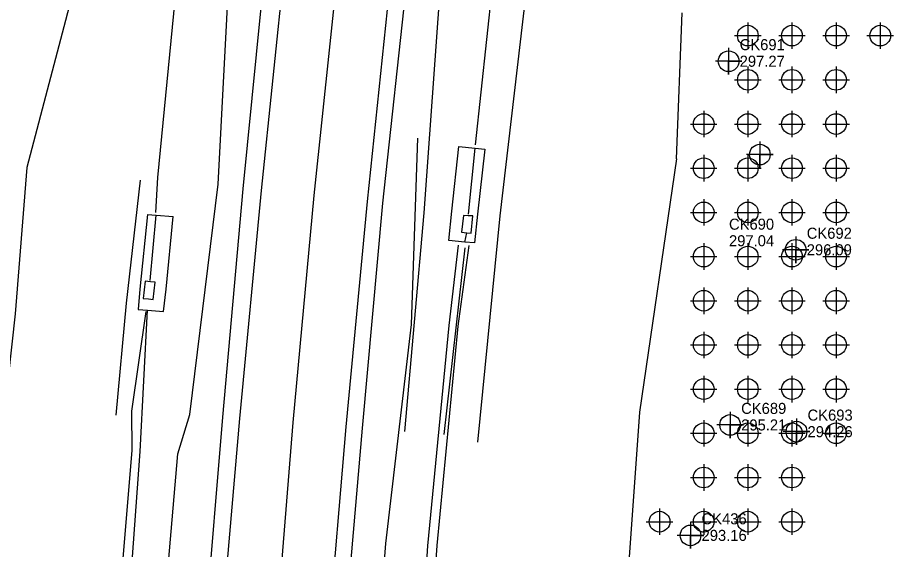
# Model space of a CAD drawing. Extents: x 1941547 to 1942851, y 663002 to 668358.
# Drawn here: x 1941924.5 to 1942123, y 667943.7 to 668064.1 of the extents above; entities that cross this region are included whole.
import ezdxf

# ---------------------------------------------------------------- set-up
doc = ezdxf.new("R2010")
doc.units = 0
for name, color, linetype in [('CTL GPS Vertical Cogo Elevation', 7, 'Continuous'), ('CTL NGS Vertical CELL', 7, 'Continuous'), ('Exist DTM Drainline Cogo Elevation', 7, 'Continuous'), ('Exist DTM QL2 LIDAR Elevation Point', 7, 'Continuous'), ('Exist Property Iron Pin Cogo Number', 7, 'Continuous'), ('Exist Roads EOP Cogo Point CELL', 7, 'Continuous'), ('Exist Roads EOT', 7, 'Continuous'), ('Exist Structure Minor Paved Ditch or Gutter', 7, 'Continuous'), ('Exist Utilities Telephone UG Cable SUE LOS C Cogo Elevation', 7, 'Continuous'), ('Exist Utilities Telephone UG FO SUE LOS C Cogo Elevation', 7, 'Continuous')]:
    doc.layers.add(name, color=color, linetype=linetype)

msp = doc.modelspace()

# ---------------------------------------------------------------- linework, layer by layer
at = {"layer": 'CTL NGS Vertical CELL'}
for p, q in [((1942026.7, 668019.61), (1942028.2, 668034.54)), ((1941954.6, 668004.61), (1941955.92, 668019.34)), ((1942025.89, 668012.01), (1942021.09, 667969.71))]:
    msp.add_line(p, q, dxfattribs=at)
for points in [[(1942065.04, 668323.64), (1942056.78, 668277.48), (1942048.92, 668225.34), (1942041.05, 668172.9), (1942035.33, 668120.57), (1942032.08, 668071.11), (1942028.21, 668035.32)], [(1941955.9, 668019.97), (1941956.36, 668027.93), (1941961.46, 668080.53), (1941966.93, 668131.39), (1941973.27, 668184.19), (1941981.21, 668235.19), (1941987.75, 668278.42)], [(1942024.37, 668012.57), (1942022.28, 667994.37), (1942017.39, 667944.52), (1942014.27, 667895.82), (1942009.92, 667846.63), (1942007.93, 667796.15), (1942005.97, 667746.35), (1942004.4, 667697.91), (1942000.78, 667648.26), (1941999.86, 667599.46), (1941998.39, 667548.71), (1942000.68, 667500.48)], [(1942026.8, 668012.52), (1942024.33, 667994.23), (1942019.53, 667944.62), (1942016.16, 667895.49), (1942012.43, 667846.36), (1942010.79, 667795.94), (1942008.34, 667746.43), (1942008.34, 667697.72), (1942004.96, 667648.49), (1942005.04, 667599.29), (1942003.6, 667548.44), (1942003.59, 667500.58)], [(1941930.54, 667422.84), (1941928.68, 667463.46), (1941928.78, 667514.02), (1941930.06, 667568.07), (1941931.99, 667622.09), (1941933.48, 667674.51), (1941937.26, 667726.95), (1941939.71, 667779.55), (1941943.19, 667828.89), (1941946.38, 667878.43), (1941949.61, 667928.57), (1941952.29, 667965.88), (1941953.97, 667997.88)], [(1941950.55, 667966.21), (1941950.47, 667974.98), (1941953.71, 667997.57)], [(1941928.41, 667422.42), (1941926.07, 667463.45), (1941926.54, 667514.2), (1941927.95, 667567.47), (1941929.84, 667622.24), (1941931.61, 667674.49), (1941934.69, 667727.1), (1941937.88, 667779.66), (1941941.36, 667829.21), (1941944.43, 667878.58), (1941947.39, 667928.96), (1941950.55, 667966.21)]]:
    msp.add_lwpolyline(points, dxfattribs=at)
at = {"layer": 'Exist DTM Drainline Cogo Elevation'}
for points in [[(1942085.65, 668057.21), (1942085.65, 668051.21), (1942085.65, 668054.21), (1942088.65, 668054.21), (1942082.65, 668054.21)], [(1942085.65, 668057.21), (1942085.65, 668051.21), (1942085.65, 668054.21), (1942088.65, 668054.21), (1942082.65, 668054.21)], [(1942092.73, 668036.07), (1942092.73, 668030.07), (1942092.73, 668033.07), (1942095.73, 668033.07), (1942089.73, 668033.07)], [(1942100.85, 668014.53), (1942100.85, 668008.53), (1942100.85, 668011.53), (1942103.85, 668011.53), (1942097.85, 668011.53)], [(1942100.85, 668014.53), (1942100.85, 668008.53), (1942100.85, 668011.53), (1942103.85, 668011.53), (1942097.85, 668011.53)], [(1942085.99, 667974.89), (1942085.99, 667968.89), (1942085.99, 667971.89), (1942088.99, 667971.89), (1942082.99, 667971.89)], [(1942085.99, 667974.89), (1942085.99, 667968.89), (1942085.99, 667971.89), (1942088.99, 667971.89), (1942082.99, 667971.89)], [(1942101.03, 667973.37), (1942101.03, 667967.37), (1942101.03, 667970.37), (1942104.03, 667970.37), (1942098.03, 667970.37)], [(1942101.03, 667973.37), (1942101.03, 667967.37), (1942101.03, 667970.37), (1942104.03, 667970.37), (1942098.03, 667970.37)], [(1942077.02, 667949.9), (1942077.02, 667943.9), (1942077.02, 667946.9), (1942080.02, 667946.9), (1942074.02, 667946.9)]]:
    msp.add_lwpolyline(points, dxfattribs=at)
for centre in [(1942085.65, 668054.21), (1942085.65, 668054.21), (1942092.73, 668033.07), (1942100.85, 668011.53), (1942100.85, 668011.53), (1942085.99, 667971.89), (1942085.99, 667971.89), (1942101.03, 667970.37), (1942101.03, 667970.37), (1942077.02, 667946.9)]:
    msp.add_circle(centre, 2.34, dxfattribs=at)
at = {"layer": 'Exist DTM QL2 LIDAR Elevation Point'}
for points in [[(1942090, 668063), (1942090, 668060)], [(1942100, 668063), (1942100, 668060)], [(1942110, 668063), (1942110, 668060)], [(1942120, 668063), (1942120, 668060)], [(1942087, 668060), (1942090, 668060)], [(1942090, 668060), (1942093, 668060)], [(1942090, 668060), (1942090, 668057)], [(1942097, 668060), (1942100, 668060)], [(1942100, 668060), (1942103, 668060)], [(1942100, 668060), (1942100, 668057)], [(1942107, 668060), (1942110, 668060)], [(1942110, 668060), (1942113, 668060)], [(1942110, 668060), (1942110, 668057)], [(1942117, 668060), (1942120, 668060)], [(1942120, 668060), (1942123, 668060)], [(1942120, 668060), (1942120, 668057)], [(1942090, 668053), (1942090, 668050)], [(1942100, 668053), (1942100, 668050)], [(1942110, 668053), (1942110, 668050)], [(1942087, 668050), (1942090, 668050)], [(1942090, 668050), (1942093, 668050)], [(1942090, 668050), (1942090, 668047)], [(1942097, 668050), (1942100, 668050)], [(1942100, 668050), (1942103, 668050)], [(1942100, 668050), (1942100, 668047)], [(1942107, 668050), (1942110, 668050)], [(1942110, 668050), (1942113, 668050)], [(1942110, 668050), (1942110, 668047)], [(1942080, 668043), (1942080, 668040)], [(1942090, 668043), (1942090, 668040)], [(1942100, 668043), (1942100, 668040)], [(1942110, 668043), (1942110, 668040)], [(1942077, 668040), (1942080, 668040)], [(1942080, 668040), (1942083, 668040)], [(1942080, 668040), (1942080, 668037)], [(1942087, 668040), (1942090, 668040)], [(1942090, 668040), (1942093, 668040)], [(1942090, 668040), (1942090, 668037)], [(1942097, 668040), (1942100, 668040)], [(1942100, 668040), (1942103, 668040)], [(1942100, 668040), (1942100, 668037)], [(1942107, 668040), (1942110, 668040)], [(1942110, 668040), (1942113, 668040)], [(1942110, 668040), (1942110, 668037)], [(1942080, 668033), (1942080, 668030)], [(1942090, 668033), (1942090, 668030)], [(1942100, 668033), (1942100, 668030)], [(1942110, 668033), (1942110, 668030)], [(1942077, 668030), (1942080, 668030)], [(1942080, 668030), (1942083, 668030)], [(1942080, 668030), (1942080, 668027)], [(1942087, 668030), (1942090, 668030)], [(1942090, 668030), (1942093, 668030)], [(1942090, 668030), (1942090, 668027)], [(1942097, 668030), (1942100, 668030)], [(1942100, 668030), (1942103, 668030)], [(1942100, 668030), (1942100, 668027)], [(1942107, 668030), (1942110, 668030)], [(1942110, 668030), (1942113, 668030)], [(1942110, 668030), (1942110, 668027)], [(1942080, 668023), (1942080, 668020)], [(1942090, 668023), (1942090, 668020)], [(1942100, 668023), (1942100, 668020)], [(1942110, 668023), (1942110, 668020)], [(1942077, 668020), (1942080, 668020)], [(1942080, 668020), (1942083, 668020)], [(1942080, 668020), (1942080, 668017)], [(1942087, 668020), (1942090, 668020)], [(1942090, 668020), (1942093, 668020)], [(1942090, 668020), (1942090, 668017)], [(1942097, 668020), (1942100, 668020)], [(1942100, 668020), (1942103, 668020)], [(1942100, 668020), (1942100, 668017)], [(1942107, 668020), (1942110, 668020)], [(1942110, 668020), (1942113, 668020)], [(1942110, 668020), (1942110, 668017)], [(1942080, 668013), (1942080, 668010)], [(1942090, 668013), (1942090, 668010)], [(1942100, 668013), (1942100, 668010)], [(1942110, 668013), (1942110, 668010)], [(1942077, 668010), (1942080, 668010)], [(1942080, 668010), (1942083, 668010)], [(1942080, 668010), (1942080, 668007)], [(1942087, 668010), (1942090, 668010)], [(1942090, 668010), (1942093, 668010)], [(1942090, 668010), (1942090, 668007)], [(1942097, 668010), (1942100, 668010)], [(1942100, 668010), (1942103, 668010)], [(1942100, 668010), (1942100, 668007)], [(1942107, 668010), (1942110, 668010)], [(1942110, 668010), (1942113, 668010)], [(1942110, 668010), (1942110, 668007)], [(1942080, 668003), (1942080, 668000)], [(1942090, 668003), (1942090, 668000)], [(1942100, 668003), (1942100, 668000)], [(1942110, 668003), (1942110, 668000)], [(1942077, 668000), (1942080, 668000)], [(1942080, 668000), (1942083, 668000)], [(1942080, 668000), (1942080, 667997)], [(1942087, 668000), (1942090, 668000)], [(1942090, 668000), (1942093, 668000)], [(1942090, 668000), (1942090, 667997)], [(1942097, 668000), (1942100, 668000)], [(1942100, 668000), (1942103, 668000)], [(1942100, 668000), (1942100, 667997)], [(1942107, 668000), (1942110, 668000)], [(1942110, 668000), (1942113, 668000)], [(1942110, 668000), (1942110, 667997)], [(1942080, 667993), (1942080, 667990)], [(1942090, 667993), (1942090, 667990)], [(1942100, 667993), (1942100, 667990)], [(1942110, 667993), (1942110, 667990)], [(1942077, 667990), (1942080, 667990)], [(1942080, 667990), (1942083, 667990)], [(1942080, 667990), (1942080, 667987)], [(1942087, 667990), (1942090, 667990)], [(1942090, 667990), (1942093, 667990)], [(1942090, 667990), (1942090, 667987)], [(1942097, 667990), (1942100, 667990)], [(1942100, 667990), (1942103, 667990)], [(1942100, 667990), (1942100, 667987)], [(1942107, 667990), (1942110, 667990)], [(1942110, 667990), (1942113, 667990)], [(1942110, 667990), (1942110, 667987)], [(1942080, 667983), (1942080, 667980)], [(1942090, 667983), (1942090, 667980)], [(1942100, 667983), (1942100, 667980)], [(1942110, 667983), (1942110, 667980)], [(1942077, 667980), (1942080, 667980)], [(1942080, 667980), (1942083, 667980)], [(1942080, 667980), (1942080, 667977)], [(1942087, 667980), (1942090, 667980)], [(1942090, 667980), (1942093, 667980)], [(1942090, 667980), (1942090, 667977)], [(1942097, 667980), (1942100, 667980)], [(1942100, 667980), (1942103, 667980)], [(1942100, 667980), (1942100, 667977)], [(1942107, 667980), (1942110, 667980)], [(1942110, 667980), (1942113, 667980)], [(1942110, 667980), (1942110, 667977)], [(1942080, 667973), (1942080, 667970)], [(1942090, 667973), (1942090, 667970)], [(1942100, 667973), (1942100, 667970)], [(1942110, 667973), (1942110, 667970)], [(1942077, 667970), (1942080, 667970)], [(1942080, 667970), (1942083, 667970)], [(1942080, 667970), (1942080, 667967)], [(1942087, 667970), (1942090, 667970)], [(1942090, 667970), (1942093, 667970)], [(1942090, 667970), (1942090, 667967)], [(1942097, 667970), (1942100, 667970)], [(1942100, 667970), (1942103, 667970)], [(1942100, 667970), (1942100, 667967)], [(1942107, 667970), (1942110, 667970)], [(1942110, 667970), (1942113, 667970)], [(1942110, 667970), (1942110, 667967)], [(1942080, 667963), (1942080, 667960)], [(1942090, 667963), (1942090, 667960)], [(1942100, 667963), (1942100, 667960)], [(1942077, 667960), (1942080, 667960)], [(1942080, 667960), (1942083, 667960)], [(1942080, 667960), (1942080, 667957)], [(1942087, 667960), (1942090, 667960)], [(1942090, 667960), (1942093, 667960)], [(1942090, 667960), (1942090, 667957)], [(1942097, 667960), (1942100, 667960)], [(1942100, 667960), (1942103, 667960)], [(1942100, 667960), (1942100, 667957)], [(1942070, 667953), (1942070, 667950)], [(1942080, 667953), (1942080, 667950)], [(1942090, 667953), (1942090, 667950)], [(1942100, 667953), (1942100, 667950)], [(1942067, 667950), (1942070, 667950)], [(1942070, 667950), (1942073, 667950)], [(1942070, 667950), (1942070, 667947)], [(1942077, 667950), (1942080, 667950)], [(1942080, 667950), (1942083, 667950)], [(1942080, 667950), (1942080, 667947)], [(1942087, 667950), (1942090, 667950)], [(1942090, 667950), (1942093, 667950)], [(1942090, 667950), (1942090, 667947)], [(1942097, 667950), (1942100, 667950)], [(1942100, 667950), (1942103, 667950)], [(1942100, 667950), (1942100, 667947)]]:
    msp.add_lwpolyline(points, dxfattribs=at)
for centre in [(1942090, 668060), (1942100, 668060), (1942110, 668060), (1942120, 668060), (1942090, 668050), (1942100, 668050), (1942110, 668050), (1942080, 668040), (1942090, 668040), (1942100, 668040), (1942110, 668040), (1942080, 668030), (1942090, 668030), (1942100, 668030), (1942110, 668030), (1942080, 668020), (1942090, 668020), (1942100, 668020), (1942110, 668020), (1942080, 668010), (1942090, 668010), (1942100, 668010), (1942110, 668010), (1942080, 668000), (1942090, 668000), (1942100, 668000), (1942110, 668000), (1942080, 667990), (1942090, 667990), (1942100, 667990), (1942110, 667990), (1942080, 667980), (1942090, 667980), (1942100, 667980), (1942110, 667980), (1942080, 667970), (1942090, 667970), (1942100, 667970), (1942110, 667970), (1942080, 667960), (1942090, 667960), (1942100, 667960), (1942070, 667950), (1942080, 667950), (1942090, 667950), (1942100, 667950)]:
    msp.add_circle(centre, 2.34, dxfattribs=at)
at = {"layer": 'Exist Property Iron Pin Cogo Number'}
for points in [[(1942029.46, 668331.31), (1942023.01, 668282.84), (1942016.05, 668230.03), (1942009.43, 668177.78), (1942002.96, 668125.07), (1941997.02, 668074.7), (1941991.66, 668023.79), (1941986.94, 667972.46)], [(1941986.94, 667972.46), (1941983.14, 667925.62), (1941979.11, 667875.72), (1941975.71, 667825.96), (1941972.91, 667776.76), (1941970.2, 667724.07), (1941967.78, 667672.14), (1941966.03, 667619.74), (1941964.82, 667566.56), (1941964.04, 667513.11), (1941963.9, 667463.6), (1941963.98, 667414.3)]]:
    msp.add_lwpolyline(points, dxfattribs=at)
at = {"layer": 'Exist Roads EOT'}
for points in [[(1941974.94, 667973.32), (1941979.78, 668024.95), (1941985.13, 668076.01), (1941991.01, 668126.92), (1941997.4, 668179.23), (1942004.19, 668231.52), (1942010.99, 668284.5), (1942017.64, 668332.73)], [(1942041.27, 668329.74), (1942034.74, 668281.46), (1942027.82, 668228.76), (1942021.25, 668176.51), (1942014.78, 668123.52), (1942009.06, 668073.27), (1942003.75, 668022.48), (1941998.95, 667971.48)], [(1941951.96, 667414.49), (1941951.82, 667463.66), (1941951.89, 667513.47), (1941952.66, 667567.03), (1941954.12, 667620.18), (1941955.74, 667673.09), (1941958.11, 667725.12), (1941960.9, 667778.05), (1941963.81, 667827.1), (1941967.02, 667877.05), (1941970.92, 667927.07), (1941974.94, 667973.32)], [(1941998.95, 667971.48), (1941994.9, 667924.27), (1941991.1, 667874.21), (1941987.79, 667824.66), (1941984.92, 667775.88), (1941982.17, 667722.97), (1941979.79, 667671.47), (1941977.97, 667618.81), (1941976.79, 667566.11), (1941976.12, 667512.58), (1941975.9, 667463.33), (1941975.97, 667414.74)]]:
    msp.add_lwpolyline(points, dxfattribs=at)
at = {"layer": 'Exist Structure Minor Paved Ditch or Gutter'}
for points in [[(1942030.41, 668034.28), (1942028.73, 668019.6), (1942028.05, 668013.13), (1942025.87, 668013.26), (1942022.29, 668013.66), (1942022.95, 668020.26), (1942024.5, 668034.88)], [(1941953.98, 668019.55), (1941952.27, 668002.59), (1941951.86, 667998), (1941953.97, 667997.88), (1941957.59, 667997.54), (1941958.21, 668002.65), (1941959.83, 668019.09)]]:
    msp.add_lwpolyline(points, dxfattribs=at)
at = {"layer": 'Exist Utilities Telephone UG Cable SUE LOS C Cogo Elevation'}
for points in [[(1941971.03, 667973.65), (1941975.67, 668025.36), (1941980.69, 668076.34), (1941986.93, 668127.4), (1941993.5, 668179.65), (1942000.09, 668231.99), (1942007.07, 668285.02), (1942013.37, 668333.1)], [(1942044.81, 668329.3), (1942038.47, 668280.9), (1942031.51, 668228.32), (1942024.64, 668176.05), (1942018.45, 668123.08), (1942012.73, 668072.84), (1942007.21, 668022.09), (1942002.64, 667971.13)], [(1941947.52, 667414.49), (1941948.18, 667463.95), (1941948.33, 667513.56), (1941948.74, 667567.19), (1941950.01, 667620.48), (1941951.44, 667673.18), (1941953.79, 667725.44), (1941956.78, 667778.06), (1941959.88, 667827.56), (1941963.38, 667877.42), (1941967.24, 667927.35), (1941971.03, 667973.65)], [(1942002.64, 667971.13), (1941998.56, 667923.93), (1941994.72, 667874.07), (1941991.26, 667824.47), (1941988.15, 667775.69), (1941985.27, 667722.8), (1941983.08, 667671.41), (1941981.48, 667618.83), (1941980.44, 667566), (1941979.8, 667512.63), (1941979.4, 667463.31), (1941979.4, 667414.56)]]:
    msp.add_lwpolyline(points, dxfattribs=at)
at = {"layer": 'Exist Utilities Telephone UG FO SUE LOS C Cogo Elevation'}
for p, q in [((1942073.81, 668032.13), (1942075.14, 668065.2)), ((1942025.87, 668013.26), (1942026.31, 668015.38))]:
    msp.add_line(p, q, dxfattribs=at)
for points in [[(1941979.33, 668336.88), (1941973.16, 668290.22), (1941957.68, 668233.23), (1941959.05, 668182.66), (1941951.08, 668128.66), (1941938.48, 668075.27), (1941926.68, 668030.16), (1941923.98, 667997.07), (1941921.59, 667975.09)], [(1941963.56, 667974.26), (1941969.96, 668026.4), (1941972.62, 668076.75), (1941979.78, 668129.2), (1941984.51, 668180.47), (1941993.7, 668233.8), (1941997.18, 668286.06), (1942002.92, 668333.88)], [(1942056.67, 668329.33), (1942047.84, 668279.94), (1942042.39, 668225.95), (1942034.64, 668174.64), (1942028.12, 668121.92), (1942020.36, 668072.35), (1942016.58, 668019.92), (1942012.22, 667970.41)], [(1942078.88, 668326.6), (1942067.77, 668277.54), (1942058.52, 668223.54), (1942048.2, 668172.4), (1942043.07, 668119.76), (1942039.64, 668069.04), (1942033.78, 668019.22), (1942028.79, 667968.01)], [(1942015.16, 668036.81), (1942013.71, 667994.65), (1942007.92, 667945.04), (1942004.16, 667896), (1942000.03, 667846.93), (1941998.38, 667796.26), (1941995.44, 667746.75), (1941992.37, 667698.24), (1941991.14, 667648.1), (1941991.07, 667599.08), (1941991.51, 667548.12), (1941993.3, 667500.89), (1941997.12, 667495.7), (1942004.5, 667494.55), (1942017.16, 667495.67), (1942033.91, 667493.9), (1942061.43, 667495.96)], [(1942024.5, 668034.88), (1942028.2, 668034.54), (1942030.41, 668034.28)], [(1942073.81, 668032.13), (1942065.44, 667974.81), (1942062.82, 667937.72)], [(1941946.87, 667974.1), (1941949.24, 667999.44), (1941952.39, 668027.29)], [(1941953.98, 668019.55), (1941955.92, 668019.34), (1941959.83, 668019.09)], [(1942025.59, 668019.33), (1942025.12, 668015.55), (1942026.31, 668015.38), (1942027.31, 668015.33), (1942027.71, 668019.22), (1942026.65, 668019.2), (1942025.59, 668019.33)], [(1941954.64, 668004.3), (1941953.46, 668004.43), (1941953.04, 668000.53), (1941954.21, 668000.45), (1941955.28, 668000.27), (1941955.7, 668004.19), (1941954.64, 668004.3)], [(1941938.12, 667401.41), (1941938.73, 667423.66), (1941941.78, 667464.33), (1941941.12, 667514.11), (1941938.71, 667567.68), (1941940.02, 667621.54), (1941943.32, 667673.83), (1941944.97, 667726.11), (1941947.44, 667778.97), (1941950.62, 667828.46), (1941954.58, 667878.17), (1941957.72, 667928.48), (1941960.86, 667965.38), (1941963.56, 667974.26)]]:
    msp.add_lwpolyline(points, dxfattribs=at)

# ---------------------------------------------------------------- texts
at = {"layer": 'CTL GPS Vertical Cogo Elevation'}
for s, p in [('CK691', (1942088.15, 668056.71)), ('CK690', (1942085.73, 668016.08)), ('CK692', (1942103.35, 668014.03)), ('CK689', (1942088.49, 667974.39)), ('CK693', (1942103.53, 667972.87)), ('CK436', (1942079.52, 667949.4))]:
    msp.add_text(s, height=2.5, dxfattribs=at).set_placement(p)
at = {"layer": 'Exist Roads EOP Cogo Point CELL'}
for s, p in [('297.27', (1942088.15, 668052.96)), ('297.04', (1942085.73, 668012.33)), ('296.09', (1942103.35, 668010.28)), ('295.21', (1942088.49, 667970.64)), ('294.26', (1942103.53, 667969.12)), ('293.16', (1942079.52, 667945.65))]:
    msp.add_text(s, height=2.5, dxfattribs=at).set_placement(p)

doc.saveas('drawing.dxf')
